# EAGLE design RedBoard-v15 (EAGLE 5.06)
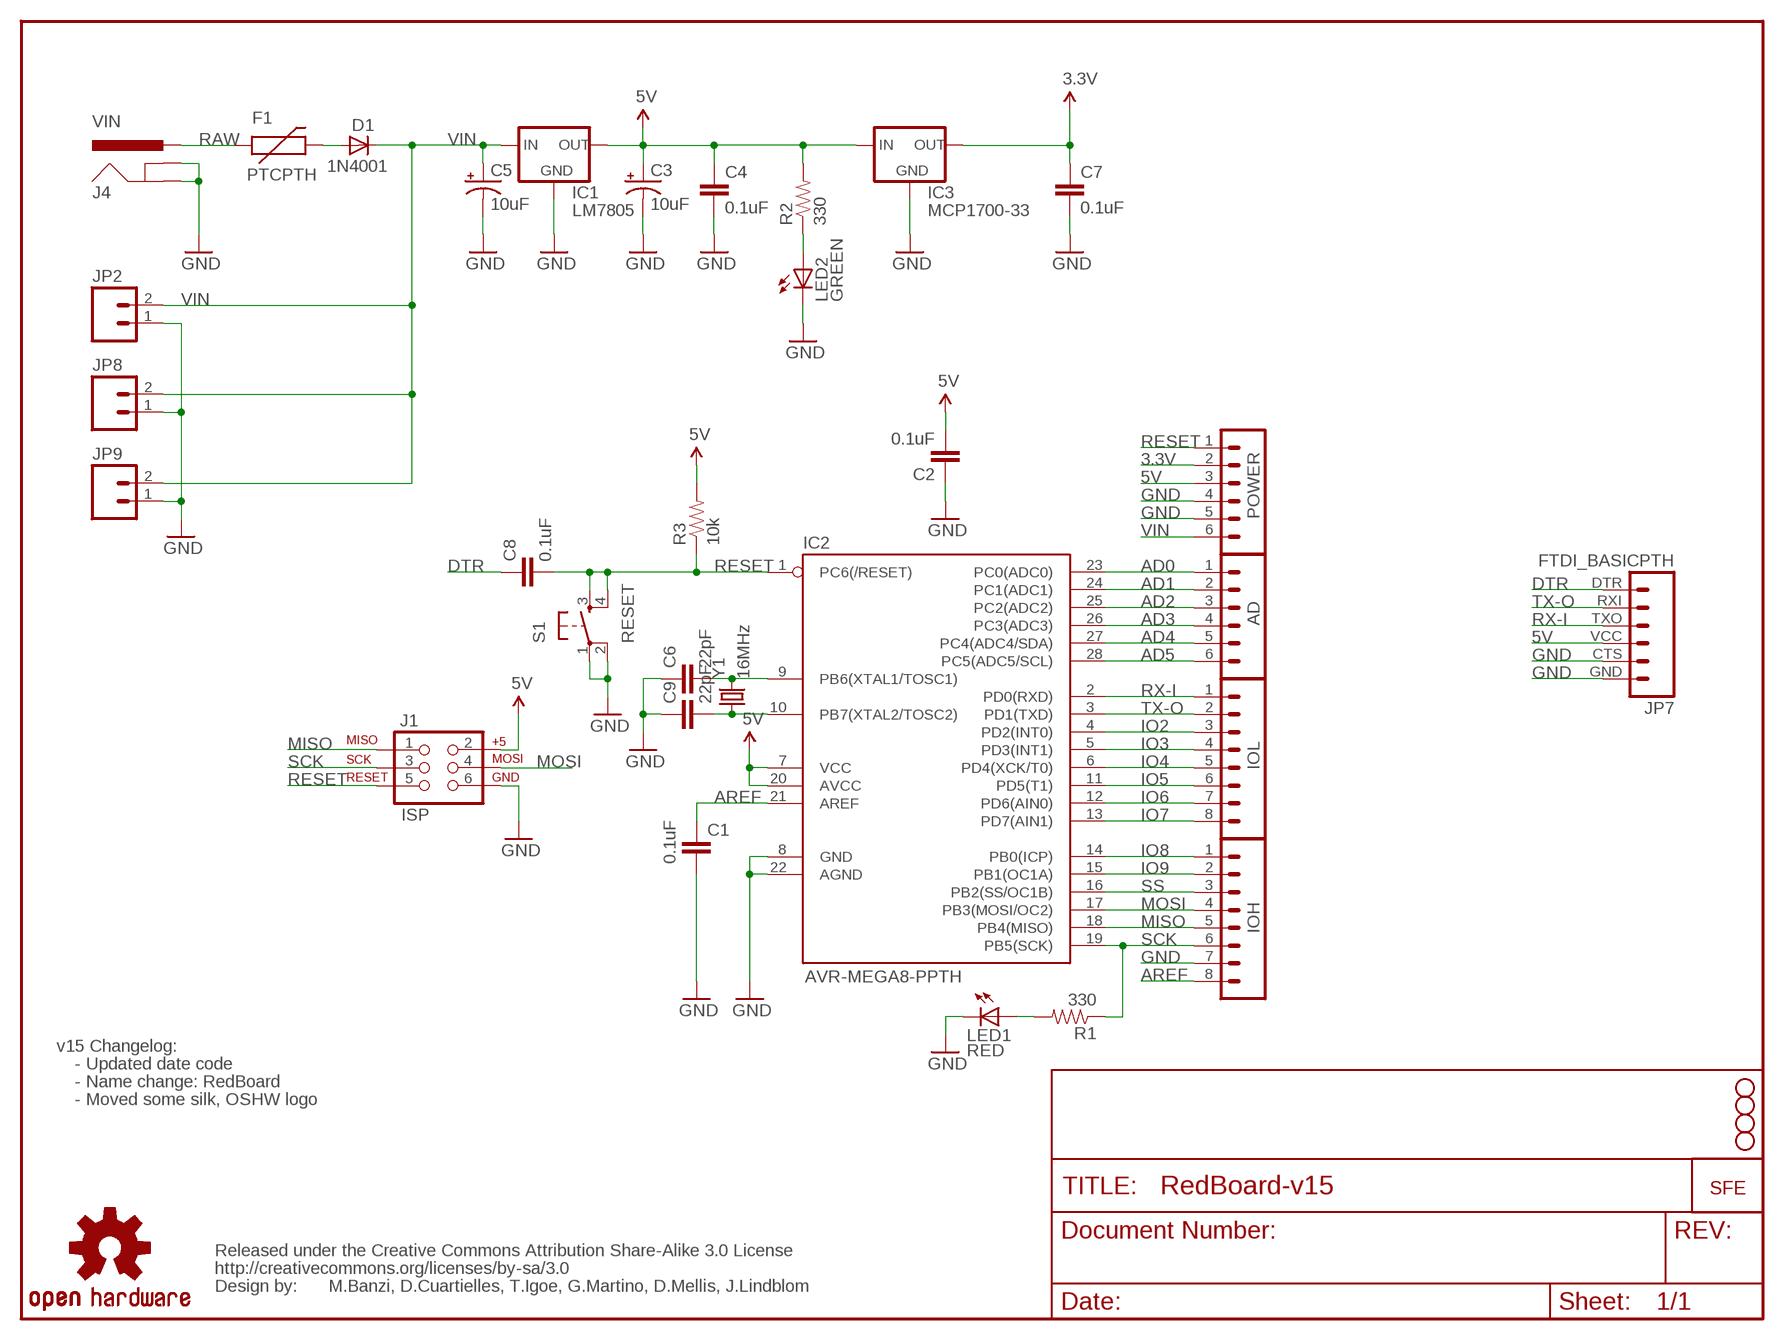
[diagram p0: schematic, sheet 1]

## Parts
AD  M06SIP  [1X06]
C1  0.1uF  CAPPTH2  [CAP-PTH-SMALL2]
C2  0.1uF  CAPPTH2  [CAP-PTH-SMALL2]
C3  10uF  CAP_POLPTH2  [CPOL-RADIAL-10UF-25V]
C4  0.1uF  CAPPTH2  [CAP-PTH-SMALL2]
C5  10uF  CAP_POLPTH2  [CPOL-RADIAL-10UF-25V]
C6  22pF  CAPPTH2  [CAP-PTH-SMALL2]
C7  0.1uF  CAPPTH2  [CAP-PTH-SMALL2]
C8  0.1uF  CAPPTH2  [CAP-PTH-SMALL2]
C9  22pF  CAPPTH2  [CAP-PTH-SMALL2]
D1  1N4001  DIODEPTH  [DIODE-1N4001]
F1  PTCPTH  [PTC]
IC1  LM7805  V_REG_78XX-TO-220  [TO-220-ALT]
IC2  AVR-MEGA8-PPTH  [DIL28-3]
IC3  MCP1700-33  V_REG_78XXTO-92  [TO-92]
IOH  M081X08  [1X08]
IOL  M081X08  [1X08]
J1  ISP  AVR_SPI_PRG_6PTH  [2X3]
J4  VIN  POWER_JACKPTH_LOCK  [POWER_JACK_PTH_LOCK]
JP1  LOGO-SFENEW  [SFE-NEW-WEBLOGO]
JP2  M02JST-PTH-2  [JST-2-PTH]
JP3  STAND-OFF  [STAND-OFF]
JP4  STAND-OFF  [STAND-OFF]
JP5  STAND-OFF  [STAND-OFF]
JP6  STAND-OFF  [STAND-OFF]
JP7  FTDI_BASICPTH  [FTDI_BASIC]
JP8  M021X02_NO_SILK  [1X02_NO_SILK]
JP9  M023.5MM-NO_SILK  [SCREWTERMINAL-3.5MM-2-NS]
LED1  RED  LED5MM  [LED5MM]
LED2  GREEN  LED5MM  [LED5MM]
POWER  M06SIP  [1X06]
R1  330  RESISTORAXIAL-0.3  [AXIAL-0.3]
R2  330  RESISTORAXIAL-0.3  [AXIAL-0.3]
R3  10k  RESISTORAXIAL-0.3  [AXIAL-0.3]
S1  RESET  TAC_SWITCHPTH  [TACTILE-PTH]
U$7  OSHW-LOGOM  [OSHW-LOGO-M]
U$15  CREATIVE_COMMONS  [CREATIVE_COMMONS]
Y1  16MHz  CRYSTALHC49US  [HC49US]

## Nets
3.3V: C7.1 IC3.3(OUT) POWER.2
5V: C2.2 C3.1(+) C4.1 IC1.OUT IC2.7(VCC) IC2.20(AVCC) IC3.2(IN) J1.2 JP7.VCC POWER.3 R2.P$2 R3.P$2
AD0: AD.1 IC2.23(PC0(ADC0))
AD1: AD.2 IC2.24(PC1(ADC1))
AD2: AD.3 IC2.25(PC2(ADC2))
AD3: AD.4 IC2.26(PC3(ADC3))
AD4: AD.5 IC2.27(PC4(ADC4/SDA))
AD5: AD.6 IC2.28(PC5(ADC5/SCL))
AREF: C1.1 IC2.21(AREF) IOH.8
DTR: C8.1 JP7.DTR
GND: C1.2 C2.1 C3.2(-) C4.2 C5.2(-) C6.1 C7.2 C9.1 IC1.GND IC2.8(GND) IC2.22(AGND) IC3.1(GND) IOH.7 J1.6 J4.GND J4.GNDBREAK JP2.1 JP7.CTS JP7.GND JP8.1 JP9.1 LED1.K(C) LED2.K(C) POWER.4 POWER.5 S1.1 S1.2
IO2: IC2.4(PD2(INT0)) IOL.3
IO3: IC2.5(PD3(INT1)) IOL.4
IO4: IC2.6(PD4(XCK/T0)) IOL.5
IO5: IC2.11(PD5(T1)) IOL.6
IO6: IC2.12(PD6(AIN0)) IOL.7
IO7: IC2.13(PD7(AIN1)) IOL.8
IO8: IC2.14(PB0(ICP)) IOH.1
IO9: IC2.15(PB1(OC1A)) IOH.2
MISO: IC2.18(PB4(MISO)) IOH.5 J1.1
MOSI: IC2.17(PB3(MOSI/OC2)) IOH.4 J1.4
N$1: LED1.A R1.P$2
N$2: LED2.A R2.P$1
N$3: C6.2 IC2.9(PB6(XTAL1/TOSC1)) Y1.2
N$4: C9.2 IC2.10(PB7(XTAL2/TOSC2)) Y1.1
N$6: D1.A F1.P$2
RAW: F1.P$1 J4.PWR
RESET: C8.2 IC2.1(PC6(/RESET)) J1.5 POWER.1 R3.P$1 S1.3 S1.4
RX-I: IC2.2(PD0(RXD)) IOL.1 JP7.TXO
SCK: IC2.19(PB5(SCK)) IOH.6 J1.3 R1.P$1
SS: IC2.16(PB2(SS/OC1B)) IOH.3
TX-O: IC2.3(PD1(TXD)) IOL.2 JP7.RXI
VIN: C5.1(+) D1.C IC1.IN JP2.2 JP8.2 JP9.2 POWER.6

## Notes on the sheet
- v15 Changelog:
- - Updated date code
- - Name change: RedBoard
- - Moved some silk, OSHW logo
- M.Banzi, D.Cuartielles, T.Igoe, G.Martino, D.Mellis, J.Lindblom

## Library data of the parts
AD POWER = SparkFun:M06: Header 6 Standard 6-pin 0.1" header. Use with straight break away headers (SKU : PRT-00116), right angle break away headers (PRT-00553), swiss pins (PRT-00743), machine pins (PRT-00117), and female headers (PRT-00115). Molex polarized connector foot print use with SKU : PRT-08094 with associated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
C1 C2 C4 C6-C9 = SparkFun:CAP: Capacitor
C3 C5 = SparkFun:CAP_POL: Capacitor Polarized
D1 = SparkFun:DIODE: Diode
F1 = SparkFun:PTC: Resettable Fuse PTC
IC1 IC3 = SparkFun:V_REG_78XX: Voltage Regulator Standard 7805 5V regulator. IGO (Input Ground Output). Spark Fun Electronics SKU : COM-00107
IC2 = SparkFun:AVR-MEGA8-P: MICROCONTROLLER 8 Kbytes FLASH 1 kbytes SRAM 512 bytes EEPROM USART 4-channel 10 bit ADC 2-channel 8 bit ADC
IOH IOL = SparkFun:M08: Header 8 Standard 8-pin 0.1" header. Use with straight break away headers (SKU : PRT-00116), right angle break away headers (PRT-00553), swiss pins (PRT-00743), machine pins (PRT-00117), and female headers (PRT-00115).
J1 = SparkFun:AVR_SPI_PRG_6: AVR ISP 6 Pin This is the reduced ISP connector for AVR programming. Common on Arduino. This footprint will take up less PCB space and can be used with a 10-pin to 6-pin adapter such as SKU: BOB-08508
J4 = SparkFun:POWER_JACK: Power Jack This is the standard 5.5mm barrel jack for power. The PTH is the most common, proven, reliable, footprint. All others are experimental. The Slot footprint only works if the mill layer is transmitted to the PCB fab house so be warned. Spark Fun Electronics SKU : PRT-00119. Mating wall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
JP1 = SparkFun:LOGO-SFE: Spark Fun Electronics PCB Logo
JP2 JP8 JP9 = SparkFun:M02: Header 2
JP3-JP6 = SparkFun:STAND-OFF: Stand Off
JP7 = SparkFun:FTDI_BASIC: FTDI Basic: 3.3V and 5V
LED1 LED2 = SparkFun:LED: LEDs
R1-R3 = SparkFun:RESISTOR: Resistor
S1 = SparkFun:TAC_SWITCH: Momentary Switch Button commonly used for reset or general input. Spark Fun Electronics SKU : COM-00097
U$7 = SparkFun:OSHW-LOGO: Open Source Hardware Logo This logo indicates the piece of hardware it is found on incorporates a OSHW license and/or adheres to the definition of open source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
U$15 = SparkFun:CREATIVE_COMMONS
Y1 = SparkFun:CRYSTAL: Crystals

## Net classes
0 default: width 0.152 mm, drill 0.305 mm, clearance 0.152 mm

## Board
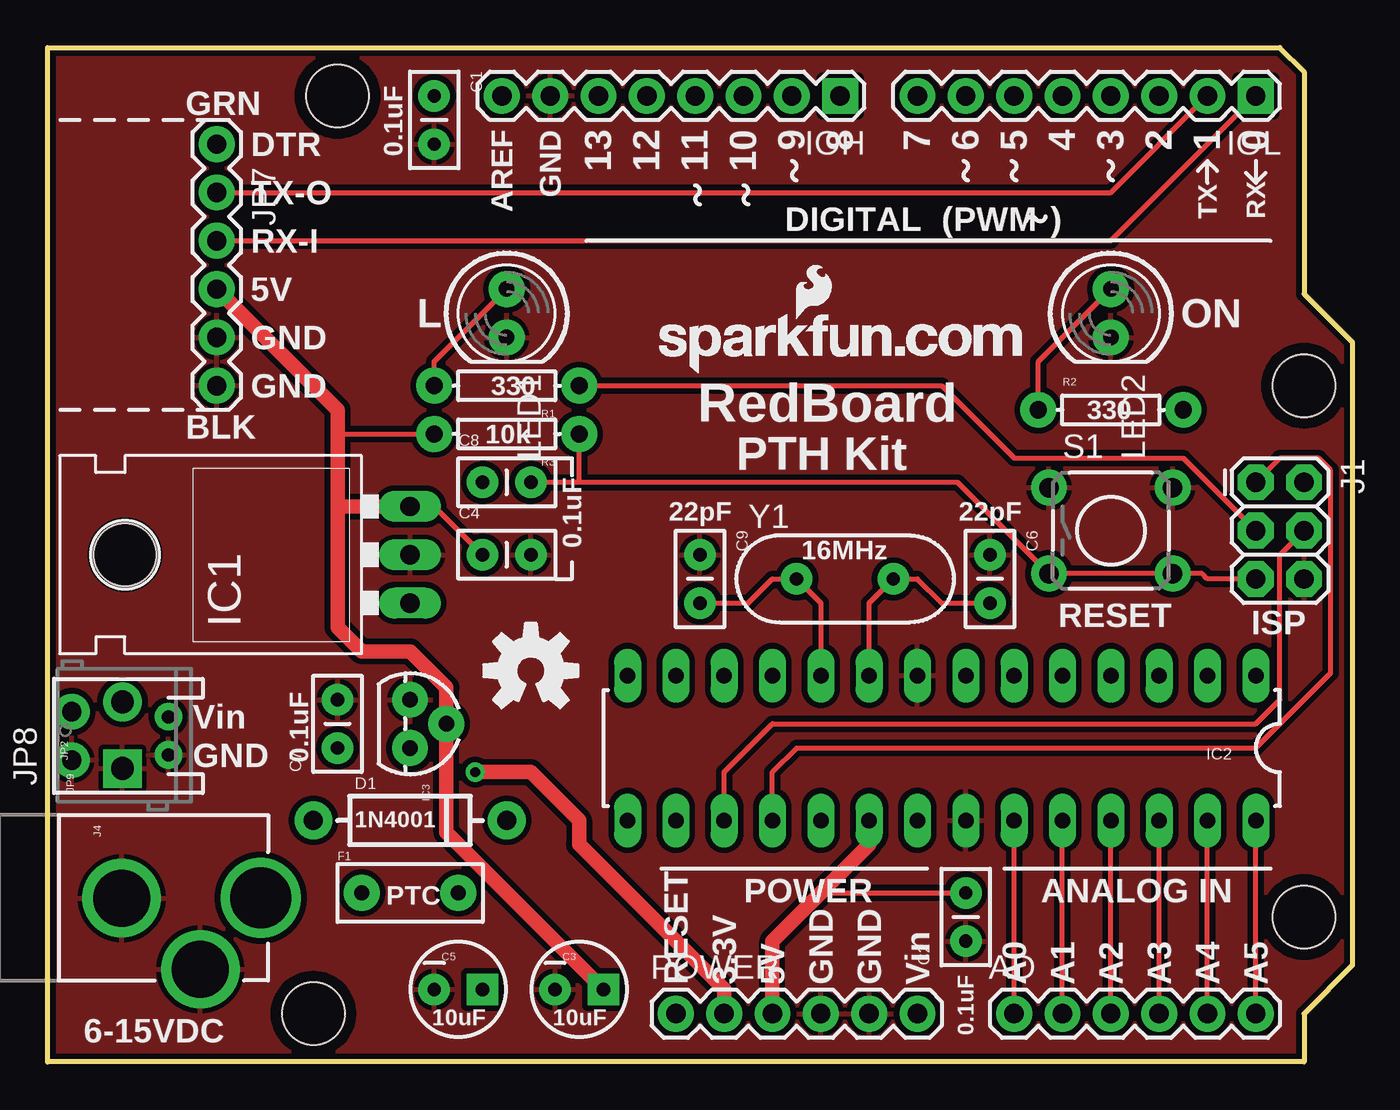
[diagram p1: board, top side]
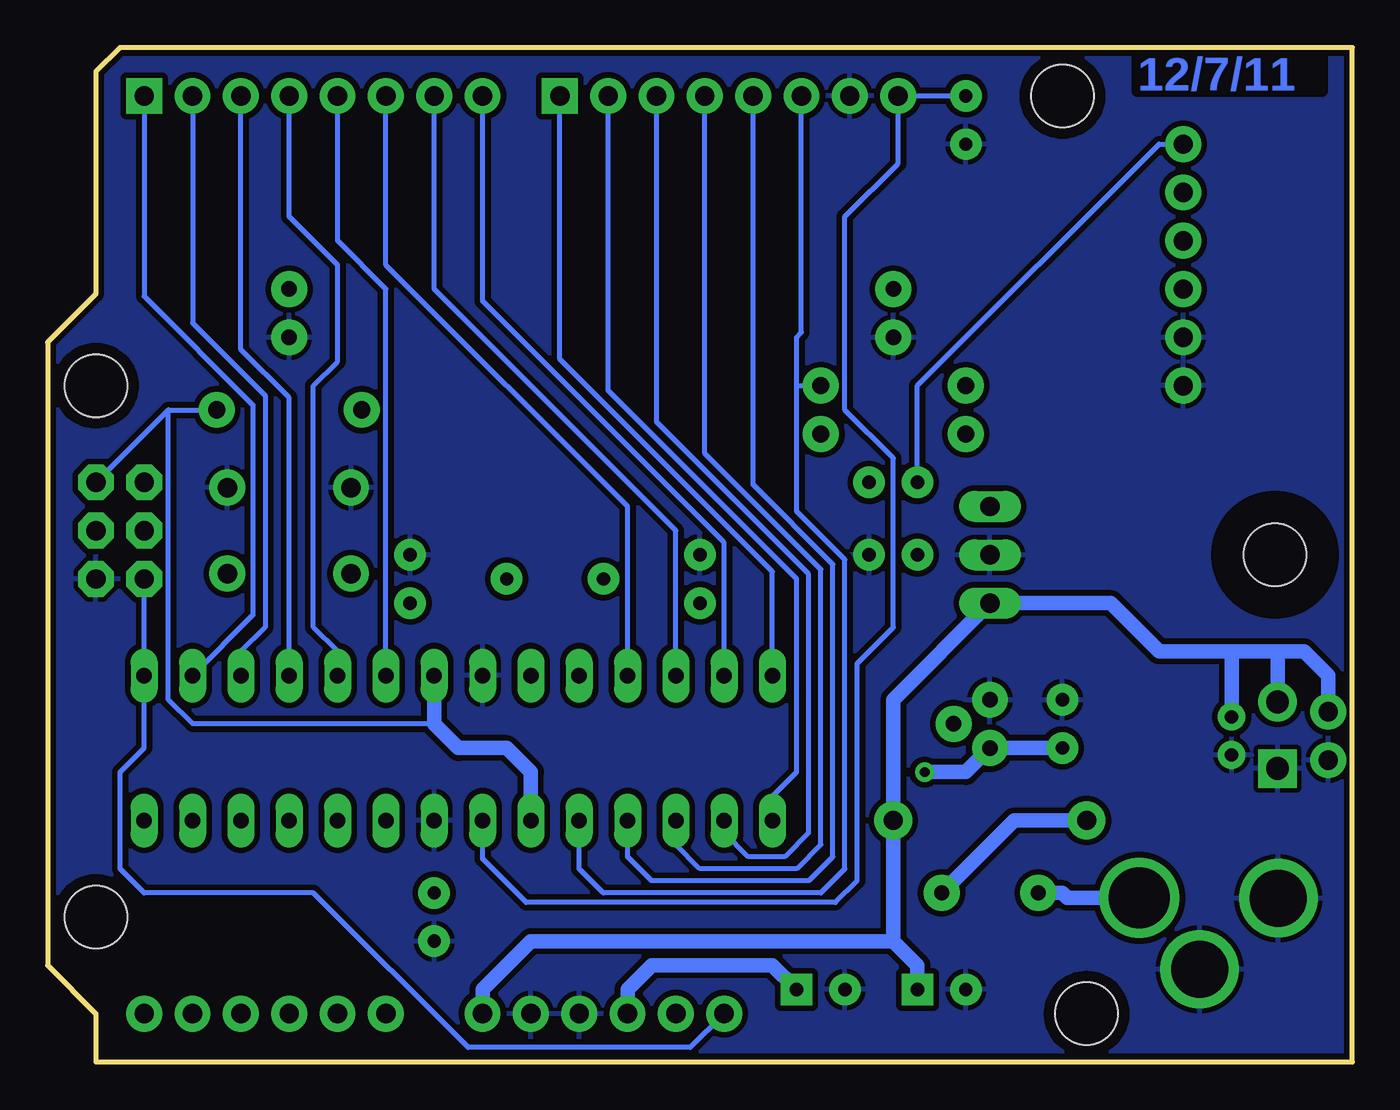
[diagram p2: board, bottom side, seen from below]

Size 68.58 x 53.34 mm. Coordinates in mm from the lower left corner, seen from the top.
Outline: 0,53.34 64.77,53.34 66.04,52.07 66.04,40.39 68.58,37.85 68.58,5.08 66.04,2.54 66.04,0 0,0 0,53.34
Copper layers (1*16): Top 0.035mm / dielectric 1.5mm / Bottom 0.035mm
Design rules "SparkFun *": minimum track width 8mil, minimum drill 20mil, track to track 8mil, track to pad 8mil, pad to pad 8mil, via to via 8mil, smd to smd 8mil, copper to edge 8mil, drill to drill 8mil, minimum pad ring 12mil, minimum via ring 10mil, stop-mask expansion 4mil, vias tented up to drill 20mil, thermal gap 10mil

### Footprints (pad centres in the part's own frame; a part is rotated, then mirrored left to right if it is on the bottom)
1X06 = drill 1.016 pad 1.88 round: 1 0,0; 2 2.54,0; 3 5.08,0; 4 7.62,0; 5 10.16,0; 6 12.7,0
CAP-PTH-SMALL2 = drill 0.7 pad 1.651 round: 1 0,0; 2 2.54,0
CPOL-RADIAL-10UF-25V = drill 0.7 pad 1.651 square: 1 1.27,0 | drill 0.7 pad 1.651 round: 2 -1.27,0
DIODE-1N4001 = drill 1 pad 1.981 round: A -5.08,0; C 5.08,0
PTC = drill 0.8 pad 1.88 round: P$1 -2.54,0; P$2 2.54,0
TO-220-ALT = drill 1.016 long: GND 0,-3.81; IN -2.54,-3.81; OUT 2.54,-3.81 | hole 3.302: 0,11.176
DIL28-3 = drill 0.813 long: 1 -16.51,-3.81; 2 -13.97,-3.81; 3 -11.43,-3.81; 4 -8.89,-3.81; 5 -6.35,-3.81; 6 -3.81,-3.81; 7 -1.27,-3.81; 8 1.27,-3.81; 9 3.81,-3.81; 10 6.35,-3.81; 11 8.89,-3.81; 12 11.43,-3.81; 13 13.97,-3.81; 14 16.51,-3.81; 15 16.51,3.81; 16 13.97,3.81; 17 11.43,3.81; 18 8.89,3.81; 19 6.35,3.81; 20 3.81,3.81; 21 1.27,3.81; 22 -1.27,3.81; 23 -3.81,3.81; 24 -6.35,3.81; 25 -8.89,3.81; 26 -11.43,3.81; 27 -13.97,3.81; 28 -16.51,3.81
TO-92 = drill 0.813 pad 1.88 round: 1 -1.27,0; 2 0,1.905; 3 1.27,0
1X08 = drill 1.016 pad 1.88 square: 1 0,0 | drill 1.016 pad 1.88 round: 2 2.54,0; 3 5.08,0; 4 7.62,0; 5 10.16,0; 6 12.7,0; 7 15.24,0; 8 17.78,0
2X3 = drill 1.016 pad 1.88 octagon: 1 0,0; 2 0,2.54; 3 2.54,0; 4 2.54,2.54; 5 5.08,0; 6 5.08,2.54
POWER_JACK_PTH_LOCK = drill 2.997 pad 4.115 round: GND 0.025,6.557; GNDBREAK 3.762,10.7 | drill 3.2 pad 4.115 round: PWR 0,13.878
JST-2-PTH = drill 0.7 pad 1.448 round: 1 -1,0; 2 1,0
STAND-OFF = hole 3.302: 0,0
FTDI_BASIC = drill 1.016 pad 1.88 round: CTS 10.16,0; DTR 0,0; GND 12.7,0; RXI 2.54,0; TXO 5.08,0; VCC 7.62,0
1X02_NO_SILK = drill 1.016 pad 1.88 round: 1 0,0; 2 2.54,0
SCREWTERMINAL-3.5MM-2-NS = drill 1.2 pad 2.032 square: 1 0,0 | drill 1.2 pad 2.032 round: 2 3.5,0
LED5MM = drill 0.813 pad 1.88 round: A -1.27,0; K 1.27,0
AXIAL-0.3 = drill 0.9 pad 1.88 round: P$1 -3.81,0; P$2 3.81,0
TACTILE-PTH = drill 1.016 pad 1.88 round: 1 -3.251,2.261; 2 3.251,2.261; 3 -3.251,-2.261; 4 3.251,-2.261
HC49US = drill 0.7 pad 1.651 round: 1 -2.54,0; 2 2.54,0

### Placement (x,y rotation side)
AD  50.8,2.54 0 top
C1  20.32,50.8 270 top
C2  48.26,6.35 90 top
C3  27.94,3.81 0 top
C4  22.86,26.67 0 top
C5  21.59,3.81 0 top
C6  49.53,26.67 270 top
C7  15.24,16.51 90 top
C8  22.86,30.48 0 top
C9  34.29,26.67 270 top
D1  19.05,12.7 0 top
F1  19.05,8.89 0 top
IC1  15.24,26.67 90 top
IC2  46.99,16.51 180 top
IC3  19.05,17.78 270 top
IOH  41.66,50.8 180 top
IOL  63.5,50.8 180 top
J1  63.5,30.48 270 top
J4  -2.67,8.64 270 top
JP1  32.13,36.2 0 top
JP2  6.35,17.14 90 top
JP3  13.97,2.54 0 top
JP4  66.04,7.62 0 top
JP5  66.04,35.56 0 top
JP6  15.24,50.8 0 top
JP7  8.89,48.26 270 top
JP8  1.27,15.88 90 top
JP9  3.94,15.43 90 top
LED1  24.13,39.37 270 top
LED2  55.88,39.37 270 top
POWER  33.02,2.54 0 top
R1  24.13,35.56 180 top
R2  55.88,34.29 0 top
R3  24.13,33.02 180 top
S1  55.88,27.94 0 top
U$7  25.4,20.57 0 top
U$15  not placed on the board
Y1  41.91,25.4 0 top

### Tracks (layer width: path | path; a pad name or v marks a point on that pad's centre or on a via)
3.3V  (via drill 0.51)
  Top 0.762: v22.48,15.24 25.4,15.24 27.94,12.7 27.94,11.43 35.56,3.81 POWER.2
  Bottom 0.762: C7.1 IC3.3 20.32,15.24 v22.48,15.24
5V
  Top 0.254: 40.64,8.89 C2.2 | C4.1 20.32,29.21 IC1.OUT | 15.24,33.02 R3.P$2
  Top 0.762: IC2.20 43.18,11.43 40.64,8.89 38.1,6.35 POWER.3 | JP7.VCC 15.24,34.29 15.24,33.02 15.24,29.21 | 15.24,29.21 15.24,22.86 16.51,21.59 19.05,21.59 20.95,19.68 IC3.2 20.95,12.06 C3.1 | 15.24,29.21 IC1.OUT
  Bottom 0.254: 48.26,17.78 60.96,17.78 62.23,19.05 62.23,34.29 | 62.23,34.29 R2.P$2 | 62.23,34.29 J1.2
  Bottom 0.762: POWER.3 38.1,3.81 36.83,5.08 30.48,5.08 C3.1 | IC2.20 43.18,15.24 44.45,16.51 46.99,16.51 48.26,17.78 IC2.7
AD0
  Top 0.254: AD.1 IC2.23
AD1
  Top 0.254: AD.2 IC2.24
AD2
  Top 0.254: AD.3 IC2.25
AD3
  Top 0.254: AD.4 IC2.26
AD4
  Top 0.254: AD.5 IC2.27
AD5
  Top 0.254: AD.6 IC2.28
AREF
  Bottom 0.254: IC2.21 45.72,10.67 43.43,8.38 27.18,8.38 26.04,9.53 26.04,20.95 24.13,22.86 24.13,31.75 26.67,34.29 26.67,44.45 23.88,47.24 IOH.8 C1.1
DTR
  Bottom 0.254: JP7.DTR 10.16,48.26 22.86,35.56 C8.1
GND
  pour Bottom (isolate 0.305): 0,53.34 0,0 66.04,0 66.04,2.54 68.58,5.08 68.58,38.1 66.04,40.64 66.04,52.07 64.77,53.34
  pour Top (isolate 0.305): 0,53.34 0,0 66.04,0 66.04,2.54 68.58,5.08 68.58,38.1 66.04,40.64 66.04,52.07 64.77,53.34
IO2
  Bottom 0.254: IC2.4 55.88,34.92 58.42,37.47 IOL.3
IO3
  Bottom 0.254: IC2.5 53.34,21.59 54.61,22.86 54.61,35.56 53.34,36.83 53.34,41.91 55.88,44.45 IOL.4
IO4
  Bottom 0.254: IC2.6 50.8,40.64 53.34,43.18 IOL.5
IO5
  Bottom 0.254: IOL.6 50.8,41.91 38.1,29.21 IC2.11
IO6
  Bottom 0.254: IOL.7 48.26,40.64 35.56,27.94 IC2.12
IO7
  Bottom 0.254: IOL.8 45.72,40.01 33.02,27.3 IC2.13
IO8
  Bottom 0.254: IC2.14 30.48,25.78 41.66,36.96 IOH.1
IO9
  Bottom 0.254: IC2.15 30.48,13.97 29.21,15.24 29.21,25.4 39.12,35.31 IOH.2
MISO
  Top 0.254: J1.1 64.77,31.75 66.8,31.75 67.44,31.11 67.44,20.45 63.5,16.51 39.37,16.51 38.1,15.24 IC2.18
  Bottom 0.254: IC2.18 38.1,10.79 36.83,9.53 28.57,9.53 27.3,10.79 27.3,26.16 31.5,30.35 IOH.5
MOSI
  Top 0.254: IC2.17 35.56,15.24 38.1,17.78 63.5,17.78 64.77,19.05 64.77,26.67 J1.4
  Bottom 0.254: IOH.4 34.04,32 27.94,25.91 27.94,11.43 29.21,10.16 34.29,10.16 35.56,11.43 IC2.17
N$1
  Top 0.254: R1.P$2 20.32,36.83 LED1.A
N$2
  Top 0.254: R2.P$1 52.07,36.83 LED2.A
N$3
  Top 0.254: IC2.9 43.18,24.13 Y1.2 45.72,25.4 46.99,24.13 C6.2
N$4
  Top 0.254: IC2.10 40.64,24.13 Y1.1 38.1,25.4 36.83,24.13 C9.2
N$6
  Bottom 0.762: D1.A 17.78,12.7 F1.P$2
RAW
  Bottom 0.762: J4.PWR 14.99,8.64 15.24,8.89 F1.P$1
RESET
  Top 0.254: 27.94,30.48 R3.P$1 | J1.5 60.96,25.4 60.68,25.68 S1.4 S1.3 47.83,30.48 27.94,30.48 | 27.94,30.48 C8.2
  Bottom 0.254: POWER.1 34.8,0.76 46.48,0.76 54.61,8.89 63.5,8.89 64.77,10.16 64.77,15.24 63.5,16.51 IC2.1 J1.5
RX-I
  Top 0.254: JP7.TXO 55.88,43.18 IOL.1
  Bottom 0.254: IOL.1 63.5,40.26 57.78,34.54 57.78,23.5 IC2.2
SCK
  Top 0.254: J1.3 59.69,31.75 50.8,31.75 46.99,35.56 R1.P$1
  Bottom 0.254: IC2.19 40.64,10.16 39.37,8.89 27.94,8.89 26.67,10.16 26.67,26.42 29.21,28.96 29.21,35.56 | IOH.6 28.96,38.35 29.21,38.1 29.21,35.56 | 29.21,35.56 R1.P$1
SS
  Bottom 0.254: IOH.3 36.58,33.66 28.57,25.65 28.57,12.06 29.84,10.79 31.75,10.79 33.02,12.06 IC2.16
TX-O
  Top 0.254: JP7.RXI 55.88,45.72 IOL.2
  Bottom 0.254: IC2.3 58.42,21.59 57.15,22.86 57.15,35.05 60.96,38.86 IOL.2
VIN
  Bottom 0.762: C5.1 22.86,5.08 24.13,6.35 | POWER.6 45.72,3.81 43.18,6.35 24.13,6.35 | 24.13,6.35 D1.C 24.13,19.05 IC1.IN 12.7,24.13 10.16,21.59 6.35,21.59 | JP8.2 1.27,20.32 2.54,21.59 3.81,21.59 | 3.81,21.59 6.35,21.59 | JP9.2 3.94,21.46 3.81,21.59 | 6.35,21.59 JP2.2

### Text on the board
Bottom: 12/7/11
tPlace: GRN | AREF | GND | 13 | 12 | 11 | 10 | 9 | 8 | 7 | 6 | 5 | 4 | 3 | 2 | 1 | 0 | DTR | 0.1uF | TX-O | DIGITAL | (PWM | ) | TX | RX | RX-I | 5V | L | ON | GND | GND | RedBoard | BLK | 0.1uF | PTH Kit | 22pF | 22pF | 16MHz | RESET | ISP | Vin | 0.1uF | GND | 1N4001 | PTC | POWER | ANALOG IN | RESET | 3.3V | 5V | GND | GND | Vin | A0 | A1 | A2 | A3 | A4 | A5 | 10uF | 10uF | 6-15VDC | 0.1uF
